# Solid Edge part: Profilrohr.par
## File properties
Username: psaghy
Dokumentum tartalom típus: 0
Author: psaghy
Last saved by: psaghy
Revision: 81
Sűrűség: 0,000 kg/m^3
Pontosság: 0,990
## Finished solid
Body 1: solid body, 6 faces, 6 edges, 0 vertices.
  Faces by surface: cone 2, cylinder 2, plane 2
  Edges by curve: circle 6
Bounding box of the edges (mm): 9.270 x 9.270 x 225.500, from (-4.635, -4.635, -107.75) to (4.635, 4.635, 117.75).
Cylindrical faces by radius (mm): R4 x1, R4.635 x1
Conical faces (half-angle, radius in mm at the cone's reference point): 15 deg R4.067 x2
Planar faces by outward normal: +z 1, -z 1
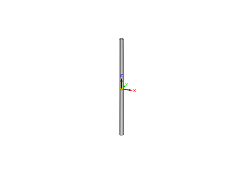
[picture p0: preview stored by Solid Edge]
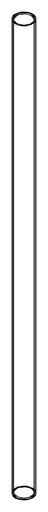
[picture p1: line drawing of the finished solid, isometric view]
